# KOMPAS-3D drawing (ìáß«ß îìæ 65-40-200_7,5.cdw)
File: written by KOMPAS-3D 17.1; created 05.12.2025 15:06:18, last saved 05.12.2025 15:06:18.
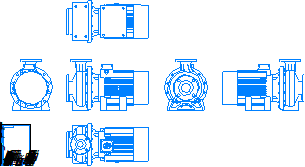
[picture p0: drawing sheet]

Sheet 1: A4, portrait

Title block, sheet 1: name: Насос МНС / 65-40-200_7,5; material: Сталь 10  ГОСТ 1050-88; mass: 174,08; sheets: 1; sheet format: A4

Views: Вид 1, Спереди, Проекционный вид 2, Проекционный вид 3, Проекционный вид 4, Проекционный вид 6
Referenced files in \\adlc.lan\data\АДЛ_ПКД\3D-модели\ADL production\Насосы ГРАНПАМП\Насосы ГРАНПАМП серии МНС\KOMPAS 3D\: Насос МНС 65-40-200_7,5.m3d
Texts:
  Andrey
  АДЛ
Dimensions and other numbers on the sheet: 1:1; 1; 65-40-200_7,5; 174,08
